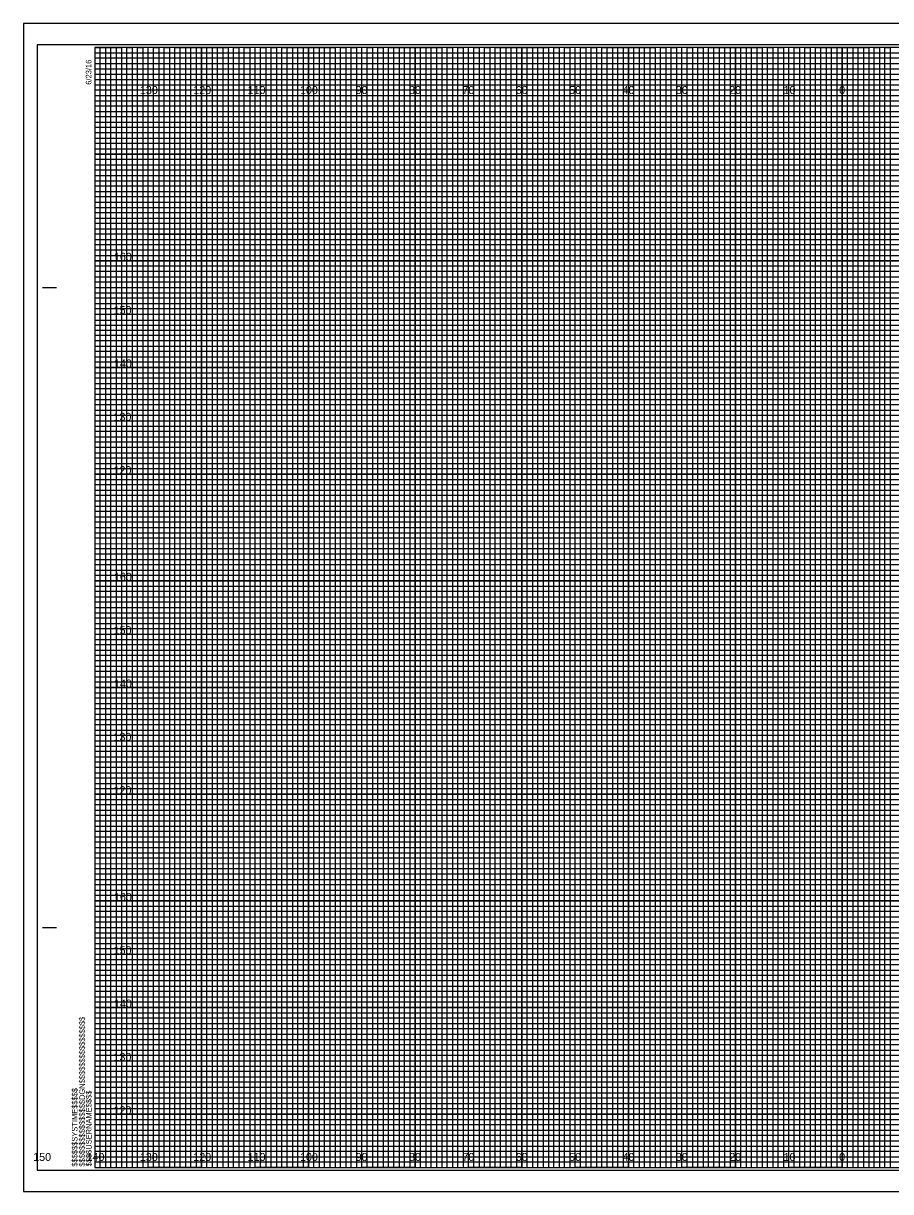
# Model space of a CAD drawing. Extents: x -13 to 323, y -5 to 3294.
# Drawn here: x -13.4 to 149.1, y 2635.5 to 2854.5 of the extents above; entities that cross this region are included whole.
import ezdxf

# ---------------------------------------------------------------- set-up
doc = ezdxf.new("R2010")
doc.units = 0
for name, color, linetype in [('Prop XS Elevation Labels', 7, 'Continuous'), ('Prop XS Offset Labels', 7, 'Continuous'), ('Scratch_Level_0', 7, 'Continuous'), ('Sheet Cross Section CELL', 7, 'Continuous'), ('Sheet Cross Section Grid Major CELL', 7, 'Continuous'), ('Sheet Cross Section Grid Middle CELL', 7, 'Continuous'), ('Sheet Cross Section Grid Minor 1 CELL', 7, 'Continuous'), ('Sheet Cross Section Grid Minor 2 CELL', 7, 'Continuous'), ('Sheet Cutting Line CELL', 7, 'Continuous'), ('Sheet DOT Grid CELL', 7, 'Continuous'), ('Sheet Plot Border Inside CELL', 7, 'Continuous'), ('Sheet Plot Border Outside CELL', 7, 'Continuous')]:
    doc.layers.add(name, color=color, linetype=linetype)

msp = doc.modelspace()

# ---------------------------------------------------------------- linework, layer by layer
at = {"layer": 'Scratch_Level_0'}
for points in [[(10, 2815), (310, 2815), (310, 2770), (10, 2770)], [(10, 2750), (320, 2750), (320, 2710), (10, 2710)], [(10, 2690), (310, 2690), (310, 2650), (10, 2650)]]:
    msp.add_lwpolyline(points, close=True, dxfattribs=at)
at = {"layer": 'Sheet Cross Section CELL'}
for p, q in [((-9.8, 2805), (-7.3, 2805)), ((-9.7, 2805), (-7.2, 2805)), ((-9.8, 2685), (-7.3, 2685)), ((-9.7, 2685), (-7.2, 2685)), ((0, 2640), (0, 2640)), ((0, 2640), (0, 2640)), ((0, 2640), (0, 2640)), ((0, 2640), (0, 2640)), ((0, 2640), (0, 2640)), ((0, 2640), (0, 2640)), ((0, 2640), (0, 2640))]:
    msp.add_line(p, q, dxfattribs=at)
msp.add_lwpolyline([(320, 2850), (0, 2850), (0, 2640), (320, 2640)], close=True, dxfattribs=at)
at = {"layer": 'Sheet Cross Section Grid Major CELL'}
for p, q in [((10, 2850), (0, 2850)), ((10, 2640), (10, 2850)), ((30, 2850), (20, 2850)), ((20, 2850), (20, 2640)), ((30, 2640), (30, 2850)), ((50, 2850), (40, 2850)), ((40, 2850), (40, 2640)), ((50, 2640), (50, 2850)), ((70, 2850), (60, 2850)), ((60, 2850), (60, 2640)), ((70, 2640), (70, 2850)), ((90, 2850), (80, 2850)), ((80, 2850), (80, 2640)), ((90, 2640), (90, 2850)), ((110, 2850), (100, 2850)), ((100, 2850), (100, 2640)), ((110, 2640), (110, 2850)), ((130, 2850), (120, 2850)), ((120, 2850), (120, 2640)), ((130, 2640), (130, 2850)), ((150, 2850), (140, 2850)), ((140, 2850), (140, 2640)), ((20, 2640), (10, 2640)), ((40, 2640), (30, 2640)), ((60, 2640), (50, 2640)), ((80, 2640), (70, 2640)), ((100, 2640), (90, 2640)), ((120, 2640), (110, 2640)), ((140, 2640), (130, 2640))]:
    msp.add_line(p, q, dxfattribs=at)
for points in [[(0, 2840), (320, 2840), (320, 2830), (0, 2830)], [(0, 2820), (320, 2820), (320, 2810), (0, 2810)], [(0, 2800), (320, 2800), (320, 2790), (0, 2790)], [(0, 2780), (320, 2780), (320, 2770), (0, 2770)], [(0, 2760), (320, 2760), (320, 2750), (0, 2750)], [(0, 2740), (320, 2740), (320, 2730), (0, 2730)], [(0, 2720), (320, 2720), (320, 2710), (0, 2710)], [(0, 2700), (320, 2700), (320, 2690), (0, 2690)], [(0, 2680), (320, 2680), (320, 2670), (0, 2670)], [(0, 2660), (320, 2660), (320, 2650), (0, 2650)]]:
    msp.add_lwpolyline(points, dxfattribs=at)
at = {"layer": 'Sheet Cross Section Grid Middle CELL'}
for points in [[(0, 2850), (5, 2850), (5, 2640), (15, 2640), (15, 2850), (25, 2850), (25, 2640), (35, 2640), (35, 2850), (45, 2850), (45, 2640), (55, 2640), (55, 2850), (65, 2850), (65, 2640), (75, 2640), (75, 2850), (85, 2850), (85, 2640), (95, 2640), (95, 2850), (105, 2850), (105, 2640), (115, 2640), (115, 2850), (125, 2850), (125, 2640), (135, 2640), (135, 2850), (145, 2850), (145, 2640), (155, 2640)], [(0, 2845), (275, 2845)], [(0, 2825), (320, 2825), (320, 2835), (0, 2835)], [(0, 2805), (320, 2805), (320, 2815), (0, 2815)], [(0, 2785), (320, 2785), (320, 2795), (0, 2795)], [(0, 2765), (320, 2765), (320, 2775), (0, 2775)], [(0, 2745), (320, 2745), (320, 2755), (0, 2755)], [(0, 2725), (320, 2725), (320, 2735), (0, 2735)], [(0, 2705), (320, 2705), (320, 2715), (0, 2715)], [(0, 2685), (320, 2685), (320, 2695), (0, 2695)], [(0, 2665), (320, 2665), (320, 2675), (0, 2675)], [(0, 2645), (320, 2645), (320, 2655), (0, 2655)]]:
    msp.add_lwpolyline(points, dxfattribs=at)
at = {"layer": 'Sheet Cross Section Grid Minor 1 CELL'}
for p, q in [((0, 2849), (260, 2849)), ((260, 2847.98), (0, 2847.98)), ((0, 2847.98), (0, 2847)), ((0, 2847), (260, 2847)), ((260, 2845.89), (0, 2845.89)), ((0, 2845.89), (0, 2844)), ((0, 2844), (320, 2844))]:
    msp.add_line(p, q, dxfattribs=at)
for points in [[(0, 2843), (270, 2843), (320, 2843), (320, 2842), (0, 2842)], [(0, 2841), (320, 2841), (320, 2839), (0, 2839)], [(0, 2838), (320, 2838), (320, 2837), (0, 2836.98)], [(0, 2836), (320, 2836), (320, 2834), (0, 2834)], [(0, 2833), (320, 2833), (320, 2832), (0, 2832)], [(0, 2831), (320, 2831), (320, 2829), (0, 2829)], [(0, 2828), (320, 2828), (320, 2827), (0, 2827)], [(0, 2826), (320, 2826), (320, 2824), (0, 2824)], [(0, 2823), (320, 2823), (320, 2822), (0, 2822)], [(0, 2821), (320, 2821), (320, 2819), (0, 2819)], [(0, 2818), (320, 2818), (320, 2817), (0, 2817)], [(0, 2816), (320, 2816), (320, 2813.95), (320, 2813), (320, 2812), (0, 2812)], [(0, 2814), (320, 2814), (320, 2813), (0, 2813)], [(0, 2811), (320, 2811), (320, 2809), (0, 2809.03)], [(0, 2809.03), (320, 2809), (320, 2808), (0, 2808)], [(0, 2807), (320, 2807), (320, 2806), (0, 2806)], [(0, 2804), (320, 2804), (320, 2803), (0, 2803)], [(0, 2802), (320, 2802), (320, 2801), (0, 2801)], [(-0.07, 2798.89), (320, 2798.89), (320, 2797.88), (-0.07, 2797.88)], [(0, 2797), (320, 2797), (320, 2796), (0, 2796)], [(0, 2794), (320, 2794), (320, 2793), (0, 2793)], [(0, 2792), (320, 2792), (320, 2791), (0, 2791)], [(0, 2789), (320, 2789), (320, 2788), (0, 2788)], [(0, 2787), (320, 2787), (320, 2786), (0, 2786)], [(0, 2784), (320, 2784), (320, 2783), (0, 2783)], [(0, 2782), (320, 2782), (320, 2781), (0, 2781)], [(0, 2779), (320, 2779), (319.99, 2777.98), (0, 2778)], [(0, 2777), (320, 2777), (320, 2776), (0, 2776)], [(0, 2774), (320, 2774), (320, 2773), (0, 2773)], [(0, 2772), (320, 2772), (320, 2771), (0, 2771)], [(0, 2769), (320, 2769), (320, 2768), (0, 2768)], [(0, 2767), (320, 2767), (320, 2766), (0, 2766)], [(0, 2764), (320, 2764), (320, 2763), (0, 2763)], [(0, 2762), (320, 2762), (320, 2761), (0, 2761)], [(0, 2759), (320, 2759), (320, 2758), (0, 2758)], [(0, 2756.99), (320.07, 2756.91), (320, 2756), (0, 2756)], [(0, 2754), (320, 2754), (320, 2753), (0, 2753)], [(0, 2752), (320, 2752), (320, 2751), (0, 2751)], [(0, 2749), (320, 2749), (320, 2748), (0, 2748)], [(0, 2747), (320, 2747), (320, 2746), (0, 2746)], [(0, 2744), (320, 2744), (320, 2743), (0, 2743)], [(0, 2742), (320, 2742), (320, 2741), (0, 2741)], [(0, 2739), (320, 2739), (320, 2738), (0, 2738)], [(0, 2737), (320, 2737), (320, 2736), (0, 2736)], [(0, 2734), (320, 2734), (320, 2733), (0, 2733)], [(0, 2732), (320, 2732), (320, 2731), (0, 2731)], [(0, 2729), (320, 2729), (320, 2728), (0, 2728)], [(0, 2727), (320, 2727), (320, 2726), (0, 2726)], [(0, 2724), (320, 2724), (320, 2723), (0, 2723)], [(0, 2722), (320, 2722), (320, 2721), (0, 2721)], [(0, 2719), (320, 2719), (319.99, 2717.98), (0, 2718)], [(0, 2717), (320, 2717), (320, 2716), (0, 2716)], [(0, 2714), (320, 2714), (320, 2713), (0, 2713)], [(0, 2712), (320, 2712), (320, 2711), (0, 2711)], [(0, 2709), (320, 2709), (320, 2708), (0, 2708)], [(0, 2707), (320, 2707), (320, 2706), (0, 2706)], [(0, 2704), (320, 2704), (320, 2703), (0, 2703)], [(0, 2702), (320, 2702), (320, 2701), (0, 2701)], [(0, 2699), (320, 2699), (320, 2698), (0, 2698)], [(0, 2696.99), (320.07, 2696.91), (320, 2696), (0, 2696)], [(0, 2694), (320, 2694), (320, 2693), (0, 2693)], [(0, 2692), (320, 2692), (320, 2691), (0, 2691)], [(0, 2689), (320, 2689), (320, 2688), (0, 2688)], [(0, 2687), (320, 2687), (320, 2686), (0, 2686)], [(0, 2684), (320, 2684), (320, 2683), (0, 2683)], [(0, 2682), (320, 2682), (320, 2681), (0, 2681)], [(0, 2679), (320, 2679), (320, 2678), (0, 2678)], [(0, 2677), (320, 2677), (320, 2676), (0, 2676)], [(0, 2674), (320, 2674), (320, 2673), (0, 2673)], [(0, 2672), (320, 2672), (320, 2671), (0, 2671)], [(0, 2669), (320, 2669), (320, 2668), (0, 2668)], [(0, 2667), (320, 2667), (320, 2666), (0, 2666)], [(0, 2664), (320, 2664), (320, 2663), (0, 2663)], [(0, 2662), (320, 2662), (320, 2661), (0, 2661)], [(0, 2659), (320, 2659), (320, 2658), (0, 2658)], [(0, 2657), (320, 2657), (320, 2656), (0, 2656)], [(0, 2654), (320, 2654), (320, 2653), (0, 2653)], [(0, 2652), (320, 2652), (320, 2651), (0, 2651)], [(0, 2649), (320, 2649), (320, 2648), (0, 2648)], [(0, 2647), (320, 2647), (320, 2646), (0, 2646)], [(0, 2644), (320, 2644), (320, 2643), (0, 2643)], [(0, 2642), (320, 2642), (320, 2641), (0, 2641)]]:
    msp.add_lwpolyline(points, dxfattribs=at)
at = {"layer": 'Sheet Cross Section Grid Minor 2 CELL'}
for points in [[(0, 2640), (1, 2640), (1, 2850), (2, 2850), (2, 2640)], [(2, 2640), (3, 2640), (3, 2850), (4, 2850), (4, 2640)], [(5, 2640), (6, 2640), (6, 2850), (7, 2850), (7, 2640)], [(7, 2640), (8, 2640), (8, 2850), (9, 2850), (9, 2640)], [(10, 2640), (11, 2640), (11, 2850), (12, 2850), (12, 2640)], [(12, 2640), (13, 2640), (13, 2850), (14, 2850), (14, 2640)], [(15, 2640), (16, 2640), (16, 2850), (17, 2850), (17, 2640)], [(17, 2640), (18, 2640), (18, 2850), (19, 2850), (19, 2640)], [(20, 2640), (21, 2640), (21, 2850), (22, 2850), (22, 2640)], [(22, 2640), (23, 2640), (23, 2850), (24, 2850), (24, 2640)], [(25, 2640), (26, 2640), (26, 2850), (27, 2850), (27, 2640)], [(27, 2640), (28, 2640), (28, 2850), (29, 2850), (29, 2640)], [(30, 2640), (31, 2640), (31, 2850), (32, 2850), (32, 2640)], [(32, 2640), (33, 2640), (33, 2850), (34, 2850), (34, 2640)], [(35, 2640), (36, 2640), (36, 2850), (37, 2850), (37, 2640)], [(37, 2640), (38, 2640), (38, 2850), (39, 2850), (39, 2640)], [(40, 2640), (41, 2640), (41, 2850), (42, 2850), (42, 2640)], [(42, 2640), (43, 2640), (43, 2850), (44, 2850), (44, 2640)], [(45, 2640), (46, 2640), (46, 2850), (47, 2850), (47, 2640)], [(47, 2640), (48, 2640), (48, 2850), (49, 2850), (49, 2640)], [(50, 2640), (51, 2640), (51, 2850), (52, 2850), (52, 2640)], [(52, 2640), (53, 2640), (53, 2850), (54, 2850), (54, 2640)], [(55, 2640), (56, 2640), (56, 2850), (57, 2850), (57, 2640)], [(57, 2640), (58, 2640), (58, 2850), (59, 2850), (59, 2640)], [(60, 2640), (61, 2640), (61, 2850), (62, 2850), (62, 2640)], [(62, 2640), (63, 2640), (63, 2850), (64, 2850), (64, 2640)], [(65, 2640), (66, 2640), (66, 2850), (67, 2850), (67, 2640)], [(67, 2640), (68, 2640), (68, 2850), (69, 2850), (69, 2640)], [(70, 2640), (71, 2640), (71, 2850), (72, 2850), (72, 2640)], [(72, 2640), (73, 2640), (73, 2850), (74, 2850), (74, 2640)], [(75, 2640), (76, 2640), (76, 2850), (77, 2850), (77, 2640)], [(77, 2640), (78, 2640), (78, 2850), (79, 2850), (79, 2640)], [(80, 2640), (81, 2640), (81, 2850), (82, 2850), (82, 2640)], [(82, 2640), (83, 2640), (83, 2850), (84, 2850), (84, 2640)], [(85, 2640), (86, 2640), (86, 2850), (87, 2850), (87, 2640)], [(87, 2640), (88, 2640), (88, 2850), (89, 2850), (89, 2640)], [(90, 2640), (91, 2640), (91, 2850), (92, 2850), (92, 2640)], [(92, 2640), (93, 2640), (93, 2850), (94, 2850), (94, 2640)], [(95, 2640), (96, 2640), (96, 2850), (97, 2850), (97, 2640)], [(97, 2640), (98, 2640), (98, 2850), (99, 2850), (99, 2640)], [(100, 2640), (101, 2640), (101, 2850), (102, 2850), (102, 2640)], [(102, 2640), (103, 2640), (103, 2850), (104, 2850), (104, 2640)], [(105, 2640), (106, 2640), (106, 2850), (107, 2850), (107, 2640)], [(107, 2640), (108, 2640), (108, 2850), (109, 2850), (109, 2640)], [(110, 2640), (111, 2640), (111, 2850), (112, 2850), (112, 2640)], [(112, 2640), (113, 2640), (113, 2850), (114, 2850), (114, 2640)], [(115, 2640), (116, 2640), (116, 2850), (117, 2850), (117, 2640)], [(117, 2640), (118, 2640), (118, 2850), (119, 2850), (119, 2640)], [(120, 2640), (121, 2640), (121, 2850), (122, 2850), (122, 2640)], [(122, 2640), (123, 2640), (123, 2850), (124, 2850), (124, 2640)], [(125, 2640), (126, 2640), (126, 2850), (127, 2850), (127, 2640)], [(127, 2640), (128, 2640), (128, 2850), (129, 2850), (129, 2640)], [(130, 2640), (131, 2640), (131, 2850), (132, 2850), (132, 2640)], [(132, 2640), (133, 2640), (133, 2850), (134, 2850), (134, 2640)], [(135, 2640), (136, 2640), (136, 2850), (137, 2850), (137, 2640)], [(137, 2640), (138, 2640), (138, 2850), (139, 2850), (139, 2640)], [(140, 2640), (141, 2640), (141, 2850), (142, 2850), (142, 2640)], [(142, 2640), (143, 2640), (143, 2850), (144, 2850), (144, 2640)], [(145, 2640), (146, 2640), (146, 2850), (147, 2850), (147, 2640)], [(147, 2640), (148, 2640), (148, 2850), (149, 2850), (149, 2640)]]:
    msp.add_lwpolyline(points, dxfattribs=at)
at = {"layer": 'Sheet Cutting Line CELL'}
for p, q in [((323.3, 2854.5), (-13.4, 2854.5)), ((-13.4, 2854.5), (-13.4, 2635.5)), ((-13.4, 2635.5), (323.3, 2635.5))]:
    msp.add_line(p, q, dxfattribs=at)
at = {"layer": 'Sheet DOT Grid CELL'}
for p, q in [((10, 2640), (10, 2850)), ((20, 2640), (20, 2850)), ((30, 2640), (30, 2850)), ((40, 2640), (40, 2850)), ((50, 2640), (50, 2850)), ((60, 2640), (60, 2850)), ((70, 2640), (70, 2850)), ((80, 2640), (80, 2850)), ((90, 2640), (90, 2850)), ((100, 2640), (100, 2850)), ((110, 2640), (110, 2850)), ((120, 2640), (120, 2850)), ((130, 2640), (130, 2850)), ((140, 2640), (140, 2850)), ((0, 2840), (320, 2840)), ((0, 2830), (320, 2830)), ((0, 2820), (320, 2820)), ((0, 2810), (320, 2810)), ((0, 2800), (320, 2800)), ((0, 2790), (320, 2790)), ((0, 2780), (320, 2780)), ((0, 2770), (320, 2770)), ((0, 2760), (320, 2760)), ((0, 2750), (320, 2750)), ((0, 2740), (320, 2740)), ((0, 2730), (320, 2730)), ((0, 2720), (320, 2720)), ((0, 2710), (320, 2710)), ((0, 2700), (320, 2700)), ((0, 2690), (320, 2690)), ((0, 2680), (320, 2680)), ((0, 2670), (320, 2670)), ((0, 2660), (320, 2660)), ((0, 2650), (320, 2650))]:
    msp.add_line(p, q, dxfattribs=at)
at = {"layer": 'Sheet Plot Border Inside CELL'}
msp.add_lwpolyline([(-10.8, 2639.5), (322.4, 2639.5), (322.4, 2850.5), (-10.8, 2850.5)], close=True, dxfattribs=at)
at = {"layer": 'Sheet Plot Border Outside CELL'}
msp.add_lwpolyline([(-13.4, 2635.5), (323.3, 2635.5), (323.3, 2854.5), (-13.4, 2854.5)], close=True, dxfattribs=at)

# ---------------------------------------------------------------- texts
at = {"layer": 'Prop XS Elevation Labels'}
for s, p in [('160', (3.57, 2810)), ('150', (3.52, 2800)), ('140', (3.57, 2790)), ('130', (3.49, 2780)), ('120', (3.5, 2770)), ('160', (3.57, 2750)), ('150', (3.52, 2740)), ('140', (3.57, 2730)), ('130', (3.49, 2720)), ('120', (3.5, 2710)), ('160', (3.57, 2690)), ('150', (3.52, 2680)), ('140', (3.57, 2670)), ('130', (3.49, 2660)), ('120', (3.5, 2650))]:
    msp.add_text(s, height=1.5, dxfattribs=at).set_placement(p)
at = {"layer": 'Prop XS Offset Labels'}
for s, p in [('130', (8.44, 2841.25)), ('120', (18.44, 2841.25)), ('110', (28.62, 2841.25)), ('100', (38.44, 2841.25)), ('90', (48.86, 2841.25)), ('80', (58.86, 2841.25)), ('70', (68.86, 2841.25)), ('60', (78.86, 2841.25)), ('50', (88.86, 2841.25)), ('40', (98.86, 2841.25)), ('30', (108.86, 2841.25)), ('20', (118.86, 2841.25)), ('10', (129.04, 2841.25)), ('0', (139.45, 2841.25)), ('0', (139.45, 2841.25)), ('150', (-11.56, 2641.25)), ('140', (-1.56, 2641.25)), ('130', (8.44, 2641.25)), ('120', (18.44, 2641.25)), ('110', (28.62, 2641.25)), ('100', (38.44, 2641.25)), ('90', (48.86, 2641.25)), ('80', (58.86, 2641.25)), ('70', (68.86, 2641.25)), ('60', (78.86, 2641.25)), ('50', (88.86, 2641.25)), ('40', (98.86, 2641.25)), ('30', (108.86, 2641.25)), ('20', (118.86, 2641.25)), ('10', (129.04, 2641.25)), ('0', (139.45, 2641.25)), ('0', (139.45, 2641.25))]:
    msp.add_text(s, height=1.5, dxfattribs=at).set_placement(p)
at = {"layer": 'Sheet Cross Section CELL'}
for s, p in [('6/23/16', (-0.65, 2843)), ('$$$$$$$$$$$$$$$$DGN$$$$$$$$$$$$$$$$', (-1.88, 2640.18)), ('$$$$$$SYSTIME$$$$$', (-3.26, 2640.18)), ('$$$$USERNAME$$$$', (-0.62, 2640.23))]:
    msp.add_text(s, height=1.05, rotation=90, dxfattribs=at).set_placement(p)

doc.saveas('drawing.dxf')
